(* Logix 5000 project; controller MVI94ADMSerialIn 1756-L63 rev 11.1; software revision 11.13 *)
// Example Logic for the MVI56-ADM module.

TASK MainTask (task) : MainProgram

MODULES
   Local : 1756-L63 (rev 11.1)
      Bridge : 1756-CNB (rev 1.1)
         MVI94ADM : 1794-ACN15 (rev 4.1, Output RPI 5 ms)
            ADM : vendor 1 type 107 code 1 (rev 1.1, Output RPI 5 ms)
END_MODULES

TYPE ADMModuleDef :
STRUCT
   ReadData : INT[600];
   WriteData : INT[600];
END_STRUCT
END_TYPE

VAR_GLOBAL   (* controller tags *)
   ADM : ADMModuleDef;
   ColdBoot : BOOL;
   MJFAULTS : DINT[12] := ([0] := -491726278, [1] := 191080, [3] := -495837906, [4] := 191080);
   WarmBoot : BOOL;
END_VAR

PROGRAM MainProgram   (* routine attr 65 MainRoutine *)

ROUTINE MainRoutine   (* ladder *)
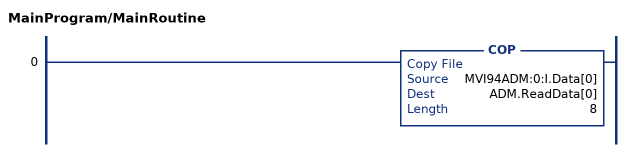
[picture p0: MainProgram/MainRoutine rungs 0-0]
   0: COP(MVI94ADM:0:I.Data[0],ADM.ReadData[0],8);
END_ROUTINE
END_PROGRAM

PROGRAM StartUp   (* routine attr 65 PowerUp *)

ROUTINE PowerUp   (* ladder *)
END_ROUTINE
END_PROGRAM
